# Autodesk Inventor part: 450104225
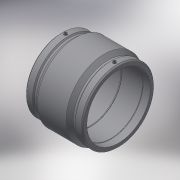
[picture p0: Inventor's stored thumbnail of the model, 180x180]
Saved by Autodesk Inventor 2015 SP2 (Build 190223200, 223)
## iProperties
Created: 2017-06
Part Number: 450104225
Material: Generic
Description: PLASSON COUPLER 225 PN25
Document SubType Name: Modeling
Designer: KIM
Mass: 8622.19 g
Surface Area: 6772.47 cm^2
Volume: 8622.19 cm^3
Density: 1 g/cm^3
Appearance: Default
Author: KIM
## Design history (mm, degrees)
derived "450104.ipt"
feature "Solid1::450104.ipt"
tag "TaggingFeature1"
body "Solid1"
other parameters: "d1" = 225, "d3" = 118, "d5" = 252, "d7" = 225, "d8" = 168 deg, "d10" = 47.2, "d11" = 15.73333, "d14" = 17.6296, "d15" = 118, "d16" = 118, "d17" = 222.75, "d18" = 225, "d19" = 3.52592, "d20" = 168 deg, "d22" = 263.2, "d24" = 255.304, "d25" = 135 deg, "d27" = 135 deg, "d30" = 15, "d31" = 84, "d34" = 5 deg, "d35" = 15, "d39" = 5 deg, "d41" = 4, "d42" = 14, "d43" = 0, "d45" = 4, "d46" = 14, "d47" = 0, "d48" = 3, "d49" = 0, "d50" = 3, "d51" = 0, "d52" = 34.22, "d53" = 8.555, "d_" = 225, "L_1" = 118, "d_2" = 12
